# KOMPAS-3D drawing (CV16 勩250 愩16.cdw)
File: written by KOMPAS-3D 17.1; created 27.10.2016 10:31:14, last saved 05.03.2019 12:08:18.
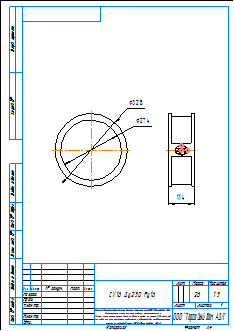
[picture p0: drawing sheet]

Sheet 1: A4, portrait

Title block, sheet 1: name: CV16 Ду250 Ру16; material: Сталь 20  ГОСТ 1050-88; mass: 26; sheets: 1; sheet format: A4; stored path: \\adlc.lan\data\АДЛ_ПКД\3D-модели\ADL production\Клапаны обратные ГРАНЛОК\CV16\KOMPAS 2D\CV16 Ду250 Ру16.cdw

Views: Вид 1, Проекционный вид 2
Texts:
  Klimkovich
  ADL
  Рама для чертежей
  Лит-Масса-Масштаб
  Материал-Предприятие
  Масштаб
  Изм.
  Лист
  № докум.
  Подп.
  Дата
  Лит.
  Разраб.
  Пров.
  Т.контр.
  Листов
  Внимание! Данный продукт является объектом авторского права ООО «Торговый Дом АДЛ».
  Запрещается изменение, копирование, распространение
  (в том числе путем копирования на другие сайты и ресурсы в Интернете)
  или любое иное использование информации и объектов без предварительного
  согласия правообладателя (ООО «Торговый Дом АДЛ»).
  Н.контр.
  Утв.
  ООО "Торговый дом АДЛ"
  Изменение
  Номер документа
  Подпись
  Обозначение документа
  Наименование изделия
  Масса изделия по ГОСТ 2.109-73
  Порядковый номер листа
  Общее количество листов в документе
  Характер работы, выполненной лицом, подписавшим документ
  Наименование или индекс предприятия, выпускающего документ
  Инв. № подл.
  Подп. и дата
  Взам. инв. №
  Инв. № дубл.
  Инвентарный номер подлинника по ГОСТ 2.501-68
  Подпись принявшего подлинник в отдел технической документации
  Инвентарный номер подлинника, взамен которого выпущен данный подлинник
  Инвентарный номер дубликата по ГОСТ 2.502-68
  Подпись принявшего дубликат в отдел технической документации
  Справ. №
  Перв. примен.
  Обозначение документа, взамен или на основании которого выпущен данный документ
  Обозначение документа, в котором впервые записан данный документ
  Подпись лица, копировавшего чертеж
  Обозначение формата листа
  !Рама для чертежа
Dimensions and other numbers on the sheet: 328; 274; 114; 1:5; 1; 26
